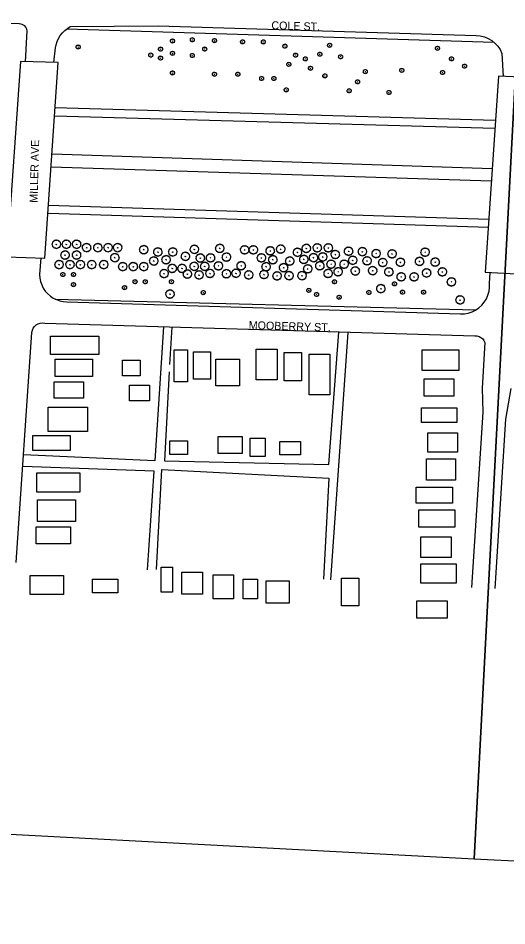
# Model space of a CAD drawing. Extents: x -9648 to 41057, y -12373 to 40276.
# Drawn here: x 15276 to 15887, y -6059 to -4925 of the extents above; entities that cross this region are included whole.
import ezdxf

# ---------------------------------------------------------------- set-up
doc = ezdxf.new("R2010")
doc.units = 0
for name, color, linetype in [('Default', 7, 'Continuous'), ('SC_Scratch1', 7, 'Continuous'), ('SH_Data', 7, 'Continuous')]:
    doc.layers.add(name, color=color, linetype=linetype)

# ---------------------------------------------------------------- blocks, each defined once
blk = doc.blocks.new('15_PIN')
at = {"layer": 'Default'}
for p, q in [((-2.8, 0), (2.8, 0)), ((0, 2.8), (0, -2.8))]:
    blk.add_line(p, q, dxfattribs=at)
for centre, start, end in [((-25.5, 4.5), 275.99, 64.01), ((-25.9, -1.5), 289.3234, 77.3433), ((-23.8, 10.3), 262.6567, 50.6766), ((-20.8, 15.5), 249.3234, 37.3433), ((-16.7, 19.8), 235.99, 24.01), ((-11.6, 23.2), 222.6567, 10.6766), ((-6, 25.2), 209.3234, 357.3433), ((0, 25.9), 195.99, 344.01), ((6, 25.2), 182.6567, 330.6766), ((11.6, 23.2), 169.3234, 317.3433), ((16.7, 19.8), 155.99, 304.01), ((20.8, 15.5), 142.6567, 290.6766), ((23.8, 10.3), 129.3234, 277.3433), ((25.5, 4.5), 115.99, 264.01), ((25.9, -1.5), 102.6567, 250.6766), ((-24.8, -7.4), 302.6567, 90.6766), ((-22.4, -13), 315.99, 104.01), ((-18.8, -17.8), 329.3234, 117.3433), ((-14.2, -21.6), 342.6567, 130.6766), ((-8.9, -24.3), 355.99, 144.01), ((-3, -25.7), 9.3234, 157.3433), ((3, -25.7), 22.6567, 170.6766), ((8.9, -24.3), 35.99, 184.01), ((14.2, -21.6), 49.3234, 197.3433), ((18.8, -17.8), 62.6567, 210.6767), ((22.4, -13), 75.99, 224.01), ((24.8, -7.4), 89.3234, 237.3433)]:
    blk.add_arc(centre, 3.05, start, end, dxfattribs=at)

msp = doc.modelspace()

# ---------------------------------------------------------------- linework, layer by layer
at = {"layer": 'SC_Scratch1'}
for p, q in [((15927.4, -4436.9), (15846.2, -5974.8)), ((15846.2, -5974.8), (15927.4, -4436.9)), ((13988.6, -5876.7), (15846.2, -5974.8)), ((15846.2, -5974.8), (17431, -6058.5))]:
    msp.add_line(p, q, dxfattribs=at)
at = {"layer": 'SH_Data'}
for p, q in [((15277.7, -4931.9), (15196.9, -4928.7)), ((15280.1, -4932.1), (15277.7, -4931.9)), ((15282.4, -4932.9), (15280.1, -4932.1)), ((15284.5, -4934.3), (15282.4, -4932.9)), ((15286.1, -4936.1), (15284.5, -4934.3)), ((15285.7, -4979.1), (15287.7, -4940.7)), ((15287.2, -4938.3), (15286.1, -4936.1)), ((15287.7, -4940.7), (15287.2, -4938.3)), ((15329, -4946.4), (15331.6, -4943.1)), ((15331.6, -4943.1), (15334.6, -4940.1)), ((15334.6, -4940.1), (15337.9, -4937.5)), ((15337.4, -4937.9), (15870.8, -4954.6)), ((15337.9, -4937.5), (15341.5, -4935.3)), ((15341.5, -4935.3), (15451.3, -4934.3)), ((15451.3, -4934.3), (15848.7, -4946.5)), ((15323.7, -4957.8), (15325.1, -4953.8)), ((15325.1, -4953.8), (15326.8, -4950)), ((15326.8, -4950), (15329, -4946.4)), ((15848.7, -4946.5), (15853.9, -4946.9)), ((15853.9, -4946.9), (15859, -4948)), ((15859, -4948), (15863.8, -4949.9)), ((15863.8, -4949.9), (15868.3, -4952.6)), ((15868.3, -4952.6), (15872.3, -4955.8)), ((15321.1, -4980), (15322.9, -4961.9)), ((15322.9, -4961.9), (15323.7, -4957.8)), ((15872.3, -4955.8), (15875.8, -4959.7)), ((15875.8, -4959.7), (15878.7, -4964)), ((15878.7, -4964), (15880.9, -4968.7)), ((15880.9, -4968.7), (15882.7, -4997.5)), ((15279.3, -4978.9), (15262.3, -5222.9)), ((15326.5, -4980.1), (15279.3, -4978.9)), ((15309.9, -5224.3), (15326.5, -4980.1)), ((15876.5, -4997.3), (15859.9, -5241.9)), ((15924.1, -4999.1), (15876.5, -4997.3)), ((15872.4, -5052.5), (15322.3, -5036.9)), ((15872.1, -5062.5), (15322, -5046.9)), ((15318.7, -5094.1), (15868.7, -5112.5)), ((15867.6, -5128.5), (15317.6, -5110.9)), ((15314.4, -5158.1), (15864.4, -5175.9)), ((15314.1, -5168.1), (15864.1, -5185.9)), ((15262.3, -5222.9), (15309.9, -5224.3)), ((15304.5, -5224.1), (15303.1, -5244.9)), ((15303.1, -5244.9), (15303.5, -5249.3)), ((15303.5, -5249.3), (15304.4, -5253.7)), ((15859.9, -5241.9), (15907.3, -5244.3)), ((15865.5, -5256.1), (15866.4, -5242.2)), ((15304.4, -5253.7), (15305.9, -5257.8)), ((15305.9, -5257.8), (15307.8, -5261.8)), ((15864.9, -5265.9), (15865.5, -5261)), ((15865.5, -5261), (15865.5, -5256.1)), ((15307.8, -5261.8), (15310.3, -5265.5)), ((15310.3, -5265.5), (15313.2, -5268.8)), ((15313.2, -5268.8), (15316.6, -5271.8)), ((15316.6, -5271.8), (15320.2, -5274.3)), ((15861.5, -5275.2), (15863.5, -5270.7)), ((15863.5, -5270.7), (15864.9, -5265.9)), ((15320.2, -5274.3), (15324.2, -5276.3)), ((15322.7, -5275.5), (15848.1, -5289.2)), ((15324.2, -5276.3), (15328.3, -5277.8)), ((15328.3, -5277.8), (15332.7, -5278.7)), ((15332.7, -5278.7), (15337.1, -5279.1)), ((15337.1, -5279.1), (15829.1, -5294.1)), ((15852.1, -5286.5), (15855.8, -5283.2)), ((15855.8, -5283.2), (15858.9, -5279.4)), ((15858.9, -5279.4), (15861.5, -5275.2)), ((15829.1, -5294.1), (15834, -5293.9)), ((15834, -5293.9), (15838.9, -5293)), ((15838.9, -5293), (15843.6, -5291.5)), ((15843.6, -5291.5), (15848, -5289.3)), ((15848, -5289.3), (15852.1, -5286.5)), ((15301.3, -5306.5), (15304, -5305.7)), ((15304, -5305.7), (15306.7, -5305.4)), ((15306.7, -5305.4), (15309.5, -5305.7)), ((15309.5, -5305.7), (15847.1, -5321.3)), ((15274, -5604.8), (15293.5, -5317.3)), ((15293.5, -5317.3), (15294.1, -5314.6)), ((15294.1, -5314.6), (15295.2, -5312)), ((15295.2, -5312), (15296.8, -5309.8)), ((15296.8, -5309.8), (15298.9, -5307.9)), ((15298.9, -5307.9), (15301.3, -5306.5)), ((15458.1, -5310.3), (15447.3, -5477.5)), ((15468.3, -5310.6), (15465.7, -5357.1)), ((15664.5, -5482.1), (15677.2, -5317)), ((15667.3, -5626.2), (15688.6, -5317.4)), ((15847.1, -5321.3), (15849.8, -5321.5)), ((15849.8, -5321.5), (15852.4, -5322.2)), ((15852.4, -5322.2), (15854.8, -5323.4)), ((15854.8, -5323.4), (15856.9, -5325.1)), ((15856.9, -5325.1), (15858.5, -5327.3)), ((15858.5, -5327.3), (15859.7, -5329.7)), ((15859.7, -5329.7), (15856.1, -5386.9)), ((15465.2, -5366.3), (15459.1, -5477.7)), ((15856.1, -5386.9), (15857.3, -5416.7)), ((15885.7, -5425.5), (15892.5, -5387.1)), ((15857.3, -5416.7), (15842.9, -5635.7)), ((15872.4, -5637.3), (15885.7, -5425.5)), ((15447.3, -5477.5), (15283.2, -5470.1)), ((15446.5, -5490.5), (15282.2, -5484.7)), ((15459.1, -5477.7), (15664.5, -5482.1)), ((15437.9, -5613.7), (15446.5, -5490.5)), ((15449.3, -5613.2), (15456.1, -5488.5)), ((15456.1, -5488.5), (15664.5, -5499.1)), ((15664.5, -5499.1), (15657.8, -5625.6))]:
    msp.add_line(p, q, dxfattribs=at)
for points in [[(15316.7, -5321.9), (15377.3, -5321.9), (15377.3, -5345), (15316.7, -5345)], [(15471.2, -5338.9), (15488.2, -5338.9), (15488.2, -5379.1), (15471.2, -5379.1)], [(15574, -5338.2), (15599.9, -5338.2), (15599.9, -5376.4), (15574, -5376.4)], [(15781.2, -5338.8), (15827.1, -5338.8), (15827.1, -5364.6), (15781.2, -5364.6)], [(15322.8, -5350.5), (15369.1, -5350.5), (15369.1, -5372.3), (15322.8, -5372.3)], [(15495.7, -5341.6), (15516.8, -5341.6), (15516.8, -5375.7), (15495.7, -5375.7)], [(15523.6, -5350.5), (15552.9, -5350.5), (15552.9, -5383.8), (15523.6, -5383.8)], [(15608.7, -5342.3), (15630.5, -5342.3), (15630.5, -5377.7), (15608.7, -5377.7)], [(15640, -5344.4), (15665.9, -5344.4), (15665.9, -5395.4), (15640, -5395.4)], [(15406.6, -5351.8), (15429, -5351.8), (15429, -5371.6), (15406.6, -5371.6)], [(15321.5, -5379.1), (15358.2, -5379.1), (15358.2, -5399.5), (15321.5, -5399.5)], [(15415.4, -5383.2), (15440.6, -5383.2), (15440.6, -5402.9), (15415.4, -5402.9)], [(15783.6, -5375.1), (15820.7, -5375.1), (15820.7, -5396.8), (15783.6, -5396.8)], [(15314, -5410.4), (15363, -5410.4), (15363, -5441), (15314, -5441)], [(15780.4, -5411.4), (15824.7, -5411.4), (15824.7, -5429.9), (15780.4, -5429.9)], [(15294.9, -5445.8), (15341.2, -5445.8), (15341.2, -5464.9), (15294.9, -5464.9)], [(15465.8, -5452.6), (15488.2, -5452.6), (15488.2, -5469.6), (15465.8, -5469.6)], [(15526.4, -5447.2), (15556.3, -5447.2), (15556.3, -5468.3), (15526.4, -5468.3)], [(15566.5, -5449.2), (15584.9, -5449.2), (15584.9, -5472.4), (15566.5, -5472.4)], [(15603.3, -5453.3), (15629.1, -5453.3), (15629.1, -5470.3), (15603.3, -5470.3)], [(15788.4, -5442.8), (15825.5, -5442.8), (15825.5, -5467), (15788.4, -5467)], [(15786.8, -5475), (15823.1, -5475), (15823.1, -5501.6), (15786.8, -5501.6)], [(15299.7, -5492.8), (15353.5, -5492.8), (15353.5, -5516.6), (15299.7, -5516.6)], [(15773.9, -5510.5), (15819.1, -5510.5), (15819.1, -5530.7), (15773.9, -5530.7)], [(15300.4, -5526.2), (15348, -5526.2), (15348, -5553.4), (15300.4, -5553.4)], [(15777.2, -5538.7), (15822.3, -5538.7), (15822.3, -5560.5), (15777.2, -5560.5)], [(15299, -5560.2), (15341.9, -5560.2), (15341.9, -5581.3), (15299, -5581.3)], [(15779.6, -5572.6), (15817.5, -5572.6), (15817.5, -5598.4), (15779.6, -5598.4)], [(15454.9, -5610.6), (15469.2, -5610.6), (15469.2, -5641.9), (15454.9, -5641.9)], [(15779.6, -5606.4), (15823.9, -5606.4), (15823.9, -5630.6), (15779.6, -5630.6)], [(15291.5, -5620.8), (15333, -5620.8), (15333, -5644.6), (15291.5, -5644.6)], [(15480.8, -5616.7), (15506.6, -5616.7), (15506.6, -5644), (15480.8, -5644)], [(15520.2, -5620.1), (15545.4, -5620.1), (15545.4, -5650.1), (15520.2, -5650.1)], [(15369.1, -5625.6), (15401.1, -5625.6), (15401.1, -5642.6), (15369.1, -5642.6)], [(15557.7, -5625.6), (15575.4, -5625.6), (15575.4, -5650.1), (15557.7, -5650.1)], [(15586.3, -5627.6), (15614.9, -5627.6), (15614.9, -5655.5), (15586.3, -5655.5)], [(15680.5, -5624.2), (15702.2, -5624.2), (15702.2, -5658.8), (15680.5, -5658.8)], [(15774.7, -5652.4), (15812.6, -5652.4), (15812.6, -5674.1), (15774.7, -5674.1)]]:
    msp.add_lwpolyline(points, close=True, dxfattribs=at)

# ---------------------------------------------------------------- block references
for p, xscale, yscale, rotation in [((15469.2, -4953.2), 0.10639346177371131, 0.10639346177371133, 64.61472397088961), ((15494.1, -4951.7), 0.10639346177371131, 0.10639346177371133, 64.61472397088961), ((15521.7, -4952.7), 0.10639346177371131, 0.10639346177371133, 64.61472397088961), ((15556.8, -4954.3), 0.10639346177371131, 0.10639346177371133, 64.61472397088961), ((15582.8, -4954.3), 0.10639346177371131, 0.10639346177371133, 64.61472397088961), ((15351.3, -4960.7), 0.10639346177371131, 0.10639346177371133, 64.61472397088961), ((15454.3, -4963.3), 0.10639346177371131, 0.10639346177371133, 64.61472397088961), ((15469.2, -4968.6), 0.10639346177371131, 0.10639346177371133, 64.61472397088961), ((15509.5, -4963.3), 0.10639346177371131, 0.10639346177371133, 64.61472397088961), ((15609.8, -4959.6), 0.10639346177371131, 0.10639346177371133, 64.61472397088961), ((15653.4, -4969.7), 0.10639346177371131, 0.10639346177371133, 64.61472397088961), ((15665.6, -4958.6), 0.10639346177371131, 0.10639346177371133, 64.61472397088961), ((15800.4, -4962.3), 0.10639346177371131, 0.10639346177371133, 64.61472397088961), ((15442.1, -4970.8), 0.10639346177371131, 0.10639346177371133, 64.61472397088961), ((15454.3, -4974.5), 0.10639346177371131, 0.10639346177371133, 64.61472397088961), ((15494.1, -4971.3), 0.10639346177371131, 0.10639346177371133, 64.61472397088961), ((15623.1, -4970.8), 0.10639346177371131, 0.10639346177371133, 64.61472397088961), ((15635.3, -4975.5), 0.10639346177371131, 0.10639346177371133, 64.61472397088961), ((15679.4, -4972.9), 0.10639346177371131, 0.10639346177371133, 64.61472397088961), ((15817.9, -4975.5), 0.10639346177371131, 0.10639346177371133, 64.61472397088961), ((15614.6, -4982.4), 0.10639346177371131, 0.10639346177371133, 64.61472397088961), ((15641.7, -4987.2), 0.10639346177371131, 0.10639346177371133, 64.61472397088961), ((15710.2, -4991.5), 0.10639346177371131, 0.10639346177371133, 64.61472397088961), ((15755.8, -4989.9), 0.10639346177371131, 0.10639346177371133, 64.61472397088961), ((15834.4, -4984.6), 0.10639346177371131, 0.10639346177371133, 64.61472397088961), ((15469.2, -4993.1), 0.10639346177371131, 0.10639346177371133, 64.61472397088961), ((15521.7, -4994.7), 0.10639346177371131, 0.10639346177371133, 64.61472397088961), ((15550.9, -4994.7), 0.10639346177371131, 0.10639346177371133, 64.61472397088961), ((15580.7, -5000), 0.10639346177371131, 0.10639346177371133, 64.61472397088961), ((15596, -5000), 0.10639346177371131, 0.10639346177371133, 64.61472397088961), ((15659.7, -4996.8), 0.10639346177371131, 0.10639346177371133, 64.61472397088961), ((15806.8, -4992.5), 0.10639346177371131, 0.10639346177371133, 64.61472397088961), ((15611.4, -5014.3), 0.10639346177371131, 0.10639346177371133, 64.61472397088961), ((15700.6, -5004.2), 0.10639346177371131, 0.10639346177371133, 64.61472397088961), ((15690, -5015.4), 0.10639346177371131, 0.10639346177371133, 64.61472397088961), ((15739.9, -5017.5), 0.10639346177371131, 0.10639346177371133, 64.61472397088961), ((15324.1, -5207.1), 0.22126578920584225, 0.22126578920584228, 64.6147239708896), ((15336.6, -5207.1), 0.22126578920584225, 0.22126578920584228, 64.6147239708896), ((15349.4, -5207.1), 0.22126578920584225, 0.22126578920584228, 64.6147239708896), ((15361.9, -5211.3), 0.22126578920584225, 0.22126578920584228, 64.6147239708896), ((15376, -5211.3), 0.22126578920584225, 0.22126578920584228, 64.6147239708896), ((15388.8, -5211.3), 0.22126578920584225, 0.22126578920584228, 64.6147239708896), ((15400.7, -5211.3), 0.22126578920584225, 0.22126578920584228, 64.6147239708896), ((15650.2, -5211.6), 0.22126578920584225, 0.22126578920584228, 64.6147239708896), ((15664, -5211.6), 0.22126578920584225, 0.22126578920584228, 64.6147239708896), ((15335, -5220.6), 0.22126578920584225, 0.22126578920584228, 64.6147239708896), ((15349.4, -5220.6), 0.22126578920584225, 0.22126578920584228, 64.6147239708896), ((15433.4, -5213.9), 0.22126578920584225, 0.22126578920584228, 64.6147239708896), ((15451, -5216.7), 0.22126578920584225, 0.22126578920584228, 64.6147239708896), ((15469.6, -5216.7), 0.22126578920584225, 0.22126578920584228, 64.6147239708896), ((15485.4, -5222.2), 0.22126578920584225, 0.22126578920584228, 64.6147239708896), ((15496.6, -5213.4), 0.22126578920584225, 0.22126578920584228, 64.6147239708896), ((15528.4, -5212.3), 0.22126578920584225, 0.22126578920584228, 64.6147239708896), ((15559.4, -5214.1), 0.22126578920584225, 0.22126578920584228, 64.6147239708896), ((15570.3, -5214.1), 0.22126578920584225, 0.22126578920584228, 64.6147239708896), ((15591.4, -5215.3), 0.22126578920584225, 0.22126578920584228, 64.6147239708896), ((15604.5, -5213.2), 0.22126578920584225, 0.22126578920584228, 64.6147239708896), ((15625.5, -5217.1), 0.22126578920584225, 0.22126578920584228, 64.6147239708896), ((15636.5, -5212.3), 0.22126578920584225, 0.22126578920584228, 64.6147239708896), ((15657.1, -5222.9), 0.22126578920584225, 0.22126578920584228, 64.6147239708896), ((15672.7, -5219.9), 0.22126578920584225, 0.22126578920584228, 64.6147239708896), ((15689.3, -5215.8), 0.22126578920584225, 0.22126578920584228, 64.6147239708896), ((15706.6, -5216.3), 0.22126578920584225, 0.22126578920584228, 64.6147239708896), ((15723.8, -5218.7), 0.22126578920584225, 0.22126578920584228, 64.6147239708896), ((15743.7, -5219.1), 0.22126578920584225, 0.22126578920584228, 64.6147239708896), ((15785, -5217), 0.22126578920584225, 0.22126578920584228, 64.6147239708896), ((15327.6, -5232.5), 0.22126578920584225, 0.22126578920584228, 64.6147239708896), ((15341.1, -5232.5), 0.22126578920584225, 0.22126578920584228, 64.6147239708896), ((15354.2, -5232.5), 0.22126578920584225, 0.22126578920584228, 64.6147239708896), ((15368.3, -5232.5), 0.22126578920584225, 0.22126578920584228, 64.6147239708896), ((15383.4, -5232.5), 0.22126578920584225, 0.22126578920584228, 64.6147239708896), ((15397.2, -5223.8), 0.22126578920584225, 0.22126578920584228, 64.6147239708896), ((15445.9, -5228), 0.22126578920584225, 0.22126578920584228, 64.6147239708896), ((15461.3, -5226.4), 0.22126578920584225, 0.22126578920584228, 64.6147239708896), ((15504, -5224.3), 0.22126578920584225, 0.22126578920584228, 64.6147239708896), ((15516.8, -5224.1), 0.22126578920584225, 0.22126578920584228, 64.6147239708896), ((15526.7, -5234.1), 0.22126578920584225, 0.22126578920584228, 64.6147239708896), ((15536.7, -5223.2), 0.22126578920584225, 0.22126578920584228, 64.6147239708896), ((15555.1, -5234), 0.22126578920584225, 0.22126578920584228, 64.6147239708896), ((15580.3, -5224.1), 0.22126578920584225, 0.22126578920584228, 64.6147239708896), ((15594.7, -5226.4), 0.22126578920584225, 0.22126578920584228, 64.6147239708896), ((15615.8, -5228.1), 0.22126578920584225, 0.22126578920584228, 64.6147239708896), ((15633.4, -5226), 0.22126578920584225, 0.22126578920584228, 64.6147239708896), ((15645.5, -5223.8), 0.22126578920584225, 0.22126578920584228, 64.6147239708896), ((15653.4, -5234), 0.22126578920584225, 0.22126578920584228, 64.6147239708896), ((15667.5, -5232), 0.22126578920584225, 0.22126578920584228, 64.6147239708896), ((15683.8, -5232), 0.22126578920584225, 0.22126578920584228, 64.6147239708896), ((15694.5, -5227.1), 0.22126578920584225, 0.22126578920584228, 64.6147239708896), ((15712.4, -5227.8), 0.22126578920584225, 0.22126578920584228, 64.6147239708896), ((15732, -5229.9), 0.22126578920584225, 0.22126578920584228, 64.6147239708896), ((15754.2, -5229.6), 0.22126578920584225, 0.22126578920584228, 64.6147239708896), ((15778, -5228.5), 0.22126578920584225, 0.22126578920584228, 64.6147239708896), ((15797.6, -5229.4), 0.22126578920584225, 0.22126578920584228, 64.6147239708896), ((15407.1, -5235), 0.22126578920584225, 0.22126578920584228, 64.6147239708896), ((15420.2, -5235), 0.22126578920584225, 0.22126578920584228, 64.6147239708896), ((15433.4, -5235), 0.22126578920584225, 0.22126578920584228, 64.6147239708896), ((15458.7, -5243.7), 0.22126578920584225, 0.22126578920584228, 64.6147239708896), ((15469, -5237.3), 0.22126578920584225, 0.22126578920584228, 64.6147239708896), ((15481.2, -5237.3), 0.22126578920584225, 0.22126578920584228, 64.6147239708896), ((15487.9, -5244.3), 0.22126578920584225, 0.22126578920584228, 64.6147239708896), ((15496.4, -5234.7), 0.22126578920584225, 0.22126578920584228, 64.6147239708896), ((15502.4, -5245.4), 0.22126578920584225, 0.22126578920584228, 64.6147239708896), ((15509.6, -5234.7), 0.22126578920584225, 0.22126578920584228, 64.6147239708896), ((15516.1, -5243.6), 0.22126578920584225, 0.22126578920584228, 64.6147239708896), ((15536.7, -5244), 0.22126578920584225, 0.22126578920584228, 64.6147239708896), ((15548.6, -5243.3), 0.22126578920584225, 0.22126578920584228, 64.6147239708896), ((15564.5, -5245.4), 0.22126578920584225, 0.22126578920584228, 64.6147239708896), ((15583.6, -5244.9), 0.22126578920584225, 0.22126578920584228, 64.6147239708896), ((15586.3, -5235.2), 0.22126578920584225, 0.22126578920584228, 64.6147239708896), ((15608.1, -5236.4), 0.22126578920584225, 0.22126578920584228, 64.6147239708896), ((15638.3, -5237.8), 0.22126578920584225, 0.22126578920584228, 64.6147239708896), ((15663.8, -5243.6), 0.22126578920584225, 0.22126578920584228, 64.6147239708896), ((15676.3, -5241.5), 0.22126578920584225, 0.22126578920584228, 64.6147239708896), ((15697.7, -5240.5), 0.22126578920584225, 0.22126578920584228, 64.6147239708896), ((15719.4, -5240.1), 0.22126578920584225, 0.22126578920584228, 64.6147239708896), ((15739.7, -5241.6), 0.22126578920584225, 0.22126578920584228, 64.6147239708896), ((15786.8, -5242.9), 0.22126578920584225, 0.22126578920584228, 64.6147239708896), ((15806.5, -5241.6), 0.22126578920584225, 0.22126578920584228, 64.6147239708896), ((15332.2, -5244.9), 0.10639346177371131, 0.10639346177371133, 64.61472397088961), ((15345.5, -5244.9), 0.10639346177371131, 0.10639346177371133, 64.61472397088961), ((15600, -5246.6), 0.22126578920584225, 0.22126578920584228, 64.6147239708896), ((15614.9, -5246.3), 0.22126578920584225, 0.22126578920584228, 64.6147239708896), ((15631.1, -5246.3), 0.22126578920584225, 0.22126578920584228, 64.6147239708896), ((15755.1, -5247.8), 0.22126578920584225, 0.22126578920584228, 64.6147239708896), ((15771.2, -5247.8), 0.22126578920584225, 0.22126578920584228, 64.6147239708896), ((15817.9, -5254.1), 0.22126578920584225, 0.22126578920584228, 64.6147239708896), ((15345.5, -5257.5), 0.10639346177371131, 0.10639346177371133, 64.61472397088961), ((15409.3, -5261.3), 0.10639346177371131, 0.10639346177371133, 64.61472397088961), ((15422.4, -5253.9), 0.10639346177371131, 0.10639346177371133, 64.61472397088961), ((15435.2, -5253.9), 0.10639346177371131, 0.10639346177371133, 64.61472397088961), ((15467.9, -5253.9), 0.10639346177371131, 0.10639346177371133, 64.61472397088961), ((15671.7, -5254), 0.10639346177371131, 0.10639346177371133, 64.61472397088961), ((15729.7, -5262.5), 0.22126578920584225, 0.22126578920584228, 64.6147239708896), ((15746.7, -5256.6), 0.10639346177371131, 0.10639346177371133, 64.61472397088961), ((15466.1, -5269.3), 0.22126578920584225, 0.22126578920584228, 64.6147239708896), ((15507.7, -5267.5), 0.10639346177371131, 0.10639346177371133, 64.61472397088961), ((15639.6, -5264.7), 0.10639346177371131, 0.10639346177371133, 64.61472397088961), ((15649.4, -5269.8), 0.10639346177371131, 0.10639346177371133, 64.61472397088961), ((15677.5, -5273.3), 0.10639346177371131, 0.10639346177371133, 64.61472397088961), ((15714.7, -5267.3), 0.10639346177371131, 0.10639346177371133, 64.61472397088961), ((15756.7, -5266.9), 0.10639346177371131, 0.10639346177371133, 64.61472397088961), ((15783.1, -5266.9), 0.10639346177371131, 0.10639346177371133, 64.61472397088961), ((15828.6, -5276.6), 0.22126578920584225, 0.22126578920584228, 64.6147239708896)]:
    msp.add_blockref('15_PIN', p, dxfattribs=dict(at, xscale=xscale, yscale=yscale, rotation=rotation))

# ---------------------------------------------------------------- texts
at = {"layer": 'SC_Scratch1'}
for s, rotation, p in [('COLE ST.', 358.2416, (15592.7, -4938.5)), ('MILLER AVE', 88.5022, (15300.6, -5155.4)), ('MOOBERRY ST.', 358.3379, (15564.4, -5313)), ('MOOBERRY ST.', 358.3379, (15564.4, -5313))]:
    msp.add_text(s, height=10, rotation=rotation, dxfattribs=at).set_placement(p)

doc.saveas('drawing.dxf')
